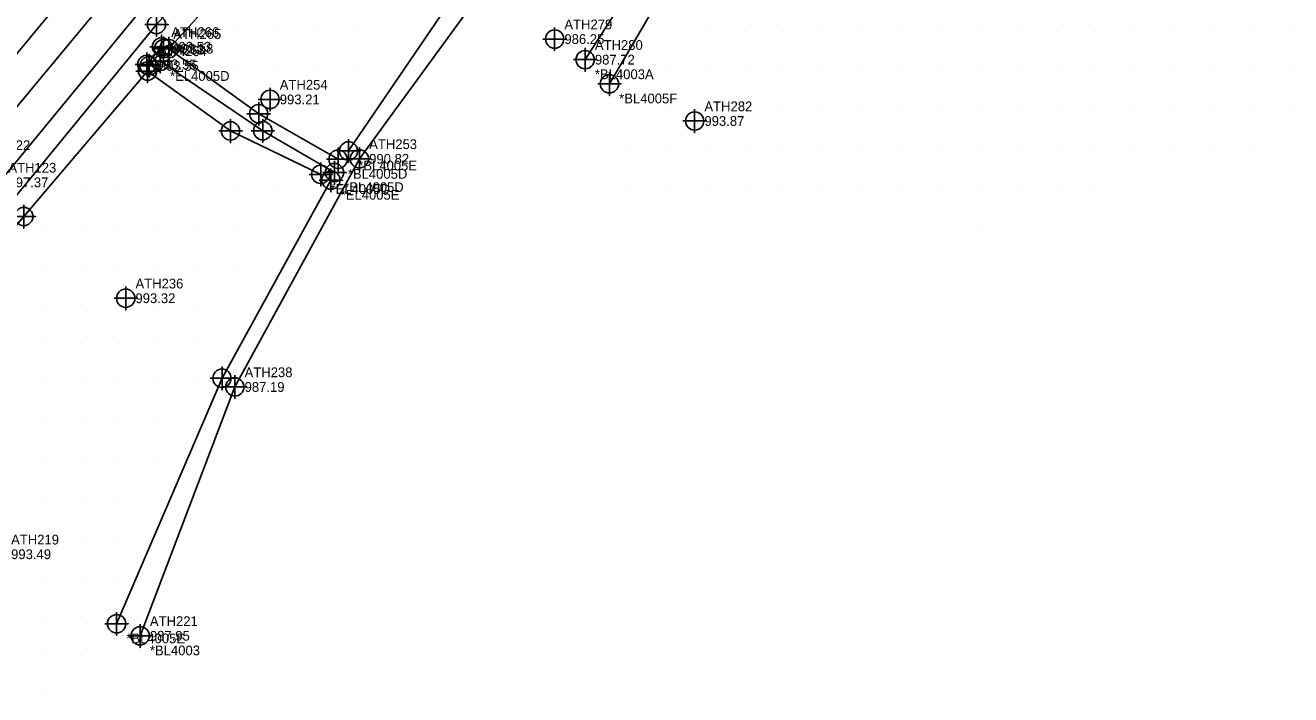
# Model space of a CAD drawing. Extents: x 1116680 to 1117499, y 661040 to 661703.
# Drawn here: x 1116855.8 to 1117180, y 661050 to 661221.5 of the extents above; entities that cross this region are included whole.
import ezdxf

# ---------------------------------------------------------------- set-up
doc = ezdxf.new("R2010")
doc.units = 0
for name, color, linetype in [('Exist DTM Breakline', 7, 'Continuous'), ('Exist DTM Breakline Cogo Comment', 7, 'Continuous'), ('Exist DTM Breakline Cogo Point CELL', 7, 'Continuous'), ('Exist DTM Crownline', 7, 'Continuous'), ('Exist DTM Crownline Cogo Number', 7, 'Continuous'), ('Exist DTM Drainline Cogo Comment', 7, 'Continuous'), ('Exist DTM Drainline Cogo Elevation', 7, 'Continuous'), ('Exist DTM Drainline Cogo Number', 7, 'Continuous'), ('Exist DTM Drainline Cogo Point CELL', 7, 'Continuous'), ('Exist DTM QL2 LIDAR Elevation Point', 7, 'Continuous'), ('Exist DTM Regular Point CELL', 7, 'Continuous'), ('Exist DTM Regular Point Cogo Elevation', 7, 'Continuous'), ('Exist DTM Regular Point Cogo Number', 7, 'Continuous'), ('Exist DTM Regular Point Underwater CELL', 7, 'Continuous'), ('Exist DTM Regular Point Underwater Cogo Elevation', 7, 'Continuous'), ('Exist DTM Regular Point Underwater Cogo Number', 7, 'Continuous'), ('Exist Hydro Stream or Body of Water', 7, 'Continuous'), ('Exist Roads EOP', 7, 'Continuous'), ('Exist Roads EOP Cogo Elevation', 7, 'Continuous'), ('Exist Roads EOP Cogo Number', 7, 'Continuous'), ('Exist Structure Major Bridge WW Cogo Elevation', 7, 'Continuous'), ('Exist Structure Major Bridge WW Cogo Number', 7, 'Continuous'), ('Exist Structure Major Bridge WW Cogo Point CELL', 7, 'Continuous')]:
    doc.layers.add(name, color=color, linetype=linetype)

msp = doc.modelspace()

# ---------------------------------------------------------------- linework, layer by layer
at = {"layer": 'Exist DTM Breakline'}
msp.add_line((1117005.474, 661206.472), (1117040.467, 661266.201), dxfattribs=at)
for points in [[(1116938.631, 661189.278), (1116970.08, 661235.53), (1117004.586, 661292.975), (1117022.365, 661331.868), (1117020.311, 661340.79)], [(1116804.214, 661119.184), (1116852.32, 661176.293), (1116889.45, 661221.661), (1116930.482, 661266.919), (1116979.857, 661313.491), (1117005.659, 661333.608)], [(1116935.96, 661187.155), (1116915.624, 661198.811), (1116892.595, 661215.476), (1116935.176, 661262.478), (1116985.662, 661308.46), (1117011.556, 661329.863)], [(1116886.991, 661211.443), (1116887.554, 661211.066), (1116891.271, 661215.491), (1116890.731, 661215.958), (1116886.991, 661211.443)], [(1116807.384, 661116.479), (1116855.455, 661172.483), (1116887.171, 661209.743), (1116908.403, 661194.399), (1116931.527, 661183.283)], [(1116935.041, 661183.755), (1116916.666, 661194.461), (1116890.415, 661212.237)], [(1116879.222, 661068.166), (1116906.229, 661131.057), (1116934.132, 661181.793)]]:
    msp.add_lwpolyline(points, dxfattribs=at)
at = {"layer": 'Exist DTM Breakline Cogo Point CELL'}
for points in [[(1116889.45, 661224.661), (1116889.45, 661218.661), (1116889.45, 661221.661), (1116892.45, 661221.661), (1116886.45, 661221.661)], [(1116892.595, 661218.476), (1116892.595, 661212.476), (1116892.595, 661215.476), (1116895.595, 661215.476), (1116889.595, 661215.476)], [(1116890.415, 661215.237), (1116890.415, 661209.237), (1116890.415, 661212.237), (1116893.415, 661212.237), (1116887.415, 661212.237)], [(1116887.171, 661212.743), (1116887.171, 661206.743), (1116887.171, 661209.743), (1116890.171, 661209.743), (1116884.171, 661209.743)], [(1117005.474, 661209.472), (1117005.474, 661203.472), (1117005.474, 661206.472), (1117008.474, 661206.472), (1117002.474, 661206.472)], [(1116915.624, 661201.811), (1116915.624, 661195.811), (1116915.624, 661198.811), (1116918.624, 661198.811), (1116912.624, 661198.811)], [(1116908.403, 661197.399), (1116908.403, 661191.399), (1116908.403, 661194.399), (1116911.403, 661194.399), (1116905.403, 661194.399)], [(1116916.666, 661197.461), (1116916.666, 661191.461), (1116916.666, 661194.461), (1116919.666, 661194.461), (1116913.666, 661194.461)], [(1116938.631, 661192.278), (1116938.631, 661186.278), (1116938.631, 661189.278), (1116941.631, 661189.278), (1116935.631, 661189.278)], [(1116935.96, 661190.155), (1116935.96, 661184.155), (1116935.96, 661187.155), (1116938.96, 661187.155), (1116932.96, 661187.155)], [(1116931.527, 661186.283), (1116931.527, 661180.283), (1116931.527, 661183.283), (1116934.527, 661183.283), (1116928.527, 661183.283)], [(1116934.132, 661184.793), (1116934.132, 661178.793), (1116934.132, 661181.793), (1116937.132, 661181.793), (1116931.132, 661181.793)], [(1116935.041, 661186.755), (1116935.041, 661180.755), (1116935.041, 661183.755), (1116938.041, 661183.755), (1116932.041, 661183.755)], [(1116855.455, 661175.483), (1116855.455, 661169.483), (1116855.455, 661172.483), (1116858.455, 661172.483), (1116852.455, 661172.483)], [(1116906.229, 661134.057), (1116906.229, 661128.057), (1116906.229, 661131.057), (1116909.229, 661131.057), (1116903.229, 661131.057)], [(1116879.222, 661071.166), (1116879.222, 661065.166), (1116879.222, 661068.166), (1116882.222, 661068.166), (1116876.222, 661068.166)]]:
    msp.add_lwpolyline(points, dxfattribs=at)
for centre in [(1116889.45, 661221.661), (1116892.595, 661215.476), (1116890.415, 661212.237), (1116887.171, 661209.743), (1117005.474, 661206.472), (1116915.624, 661198.811), (1116908.403, 661194.399), (1116916.666, 661194.461), (1116938.631, 661189.278), (1116935.96, 661187.155), (1116931.527, 661183.283), (1116934.132, 661181.793), (1116935.041, 661183.755), (1116855.455, 661172.483), (1116906.229, 661131.057), (1116879.222, 661068.166)]:
    msp.add_circle(centre, 2.344, dxfattribs=at)
at = {"layer": 'Exist DTM Crownline'}
msp.add_lwpolyline([(1116917.938, 661277.457), (1116878.296, 661230.271), (1116842.354, 661187.006), (1116792.558, 661125.963), (1116776.188, 661106.218)], dxfattribs=at)
at = {"layer": 'Exist DTM Drainline Cogo Point CELL'}
for points in [[(1116999.252, 661215.663), (1116999.252, 661209.663), (1116999.252, 661212.663), (1117002.252, 661212.663), (1116996.252, 661212.663)], [(1116941.429, 661190.261), (1116941.429, 661184.261), (1116941.429, 661187.261), (1116944.429, 661187.261), (1116938.429, 661187.261)], [(1116909.522, 661131.826), (1116909.522, 661125.826), (1116909.522, 661128.826), (1116912.522, 661128.826), (1116906.522, 661128.826)], [(1116885.259, 661068.084), (1116885.259, 661062.084), (1116885.259, 661065.084), (1116888.259, 661065.084), (1116882.259, 661065.084)]]:
    msp.add_lwpolyline(points, dxfattribs=at)
for centre in [(1116999.252, 661212.663), (1116941.429, 661187.261), (1116909.522, 661128.826), (1116885.259, 661065.084)]:
    msp.add_circle(centre, 2.344, dxfattribs=at)
at = {"layer": 'Exist DTM QL2 LIDAR Elevation Point'}
for p, q in [((1116910, 661220), (1116910, 661220)), ((1116920, 661220), (1116920, 661220)), ((1116930, 661220), (1116930, 661220)), ((1116940, 661220), (1116940, 661220)), ((1117030, 661220), (1117030, 661220)), ((1117040, 661220), (1117040, 661220)), ((1117050, 661220), (1117050, 661220)), ((1117060, 661220), (1117060, 661220)), ((1117070, 661220), (1117070, 661220)), ((1117080, 661220), (1117080, 661220)), ((1117090, 661220), (1117090, 661220)), ((1117100, 661220), (1117100, 661220)), ((1117110, 661220), (1117110, 661220)), ((1117120, 661220), (1117120, 661220)), ((1117130, 661220), (1117130, 661220)), ((1117140, 661220), (1117140, 661220)), ((1117150, 661220), (1117150, 661220)), ((1117160, 661220), (1117160, 661220)), ((1117170, 661220), (1117170, 661220)), ((1117180, 661220), (1117180, 661220)), ((1116910, 661210), (1116910, 661210)), ((1116920, 661210), (1116920, 661210)), ((1116930, 661210), (1116930, 661210)), ((1116940, 661210), (1116940, 661210)), ((1117020, 661210), (1117020, 661210)), ((1117030, 661210), (1117030, 661210)), ((1117040, 661210), (1117040, 661210)), ((1117050, 661210), (1117050, 661210)), ((1117060, 661210), (1117060, 661210)), ((1117070, 661210), (1117070, 661210)), ((1117080, 661210), (1117080, 661210)), ((1117090, 661210), (1117090, 661210)), ((1117100, 661210), (1117100, 661210)), ((1117110, 661210), (1117110, 661210)), ((1117120, 661210), (1117120, 661210)), ((1117130, 661210), (1117130, 661210)), ((1117140, 661210), (1117140, 661210)), ((1117150, 661210), (1117150, 661210)), ((1117160, 661210), (1117160, 661210)), ((1117170, 661210), (1117170, 661210)), ((1117180, 661210), (1117180, 661210)), ((1116890, 661200), (1116890, 661200)), ((1116900, 661200), (1116900, 661200)), ((1116920, 661200), (1116920, 661200)), ((1116930, 661200), (1116930, 661200)), ((1117020, 661200), (1117020, 661200)), ((1117030, 661200), (1117030, 661200)), ((1117040, 661200), (1117040, 661200)), ((1117050, 661200), (1117050, 661200)), ((1117060, 661200), (1117060, 661200)), ((1117070, 661200), (1117070, 661200)), ((1117080, 661200), (1117080, 661200)), ((1117090, 661200), (1117090, 661200)), ((1117100, 661200), (1117100, 661200)), ((1117110, 661200), (1117110, 661200)), ((1117120, 661200), (1117120, 661200)), ((1117130, 661200), (1117130, 661200)), ((1117140, 661200), (1117140, 661200)), ((1117150, 661200), (1117150, 661200)), ((1117160, 661200), (1117160, 661200)), ((1117170, 661200), (1117170, 661200)), ((1117180, 661200), (1117180, 661200)), ((1116880, 661190), (1116880, 661190)), ((1116890, 661190), (1116890, 661190)), ((1116900, 661190), (1116900, 661190)), ((1116910, 661190), (1116910, 661190)), ((1117010, 661190), (1117010, 661190)), ((1117020, 661190), (1117020, 661190)), ((1117030, 661190), (1117030, 661190)), ((1117040, 661190), (1117040, 661190)), ((1117050, 661190), (1117050, 661190)), ((1117060, 661190), (1117060, 661190)), ((1117070, 661190), (1117070, 661190)), ((1117080, 661190), (1117080, 661190)), ((1117090, 661190), (1117090, 661190)), ((1117100, 661190), (1117100, 661190)), ((1117110, 661190), (1117110, 661190)), ((1117120, 661190), (1117120, 661190)), ((1117130, 661190), (1117130, 661190)), ((1117140, 661190), (1117140, 661190)), ((1117150, 661190), (1117150, 661190)), ((1117160, 661190), (1117160, 661190)), ((1117170, 661190), (1117170, 661190)), ((1116870, 661180), (1116870, 661180)), ((1116880, 661180), (1116880, 661180)), ((1116890, 661180), (1116890, 661180)), ((1116900, 661180), (1116900, 661180)), ((1116910, 661180), (1116910, 661180)), ((1116920, 661180), (1116920, 661180)), ((1117010, 661180), (1117010, 661180)), ((1117020, 661180), (1117020, 661180)), ((1117030, 661180), (1117030, 661180)), ((1117040, 661180), (1117040, 661180)), ((1117050, 661180), (1117050, 661180)), ((1117060, 661180), (1117060, 661180)), ((1117070, 661180), (1117070, 661180)), ((1117080, 661180), (1117080, 661180)), ((1117090, 661180), (1117090, 661180)), ((1117100, 661180), (1117100, 661180)), ((1117110, 661180), (1117110, 661180)), ((1117120, 661180), (1117120, 661180)), ((1117130, 661180), (1117130, 661180)), ((1116860, 661170), (1116860, 661170)), ((1116870, 661170), (1116870, 661170)), ((1116880, 661170), (1116880, 661170)), ((1116890, 661170), (1116890, 661170)), ((1116900, 661170), (1116900, 661170)), ((1116910, 661170), (1116910, 661170)), ((1117100, 661170), (1117100, 661170)), ((1116860, 661160), (1116860, 661160)), ((1116870, 661160), (1116870, 661160)), ((1116880, 661160), (1116880, 661160)), ((1116890, 661160), (1116890, 661160)), ((1116900, 661160), (1116900, 661160)), ((1116910, 661160), (1116910, 661160)), ((1116860, 661150), (1116860, 661150)), ((1116870, 661150), (1116870, 661150)), ((1116880, 661150), (1116880, 661150)), ((1116890, 661150), (1116890, 661150)), ((1116900, 661150), (1116900, 661150)), ((1116860, 661140), (1116860, 661140)), ((1116870, 661140), (1116870, 661140)), ((1116880, 661140), (1116880, 661140)), ((1116890, 661140), (1116890, 661140)), ((1116900, 661140), (1116900, 661140)), ((1116860, 661130), (1116860, 661130)), ((1116870, 661130), (1116870, 661130)), ((1116880, 661130), (1116880, 661130)), ((1116890, 661130), (1116890, 661130)), ((1116900, 661130), (1116900, 661130)), ((1116860, 661120), (1116860, 661120)), ((1116870, 661120), (1116870, 661120)), ((1116880, 661120), (1116880, 661120)), ((1116890, 661120), (1116890, 661120)), ((1116860, 661110), (1116860, 661110)), ((1116870, 661110), (1116870, 661110)), ((1116880, 661110), (1116880, 661110)), ((1116890, 661110), (1116890, 661110)), ((1116860, 661100), (1116860, 661100)), ((1116870, 661100), (1116870, 661100)), ((1116880, 661100), (1116880, 661100)), ((1116860, 661090), (1116860, 661090)), ((1116870, 661090), (1116870, 661090)), ((1116880, 661090), (1116880, 661090)), ((1116860, 661080), (1116860, 661080)), ((1116870, 661080), (1116870, 661080)), ((1116880, 661080), (1116880, 661080)), ((1116860, 661070), (1116860, 661070)), ((1116870, 661070), (1116870, 661070)), ((1116860, 661060), (1116860, 661060)), ((1116870, 661060), (1116870, 661060)), ((1116860, 661050), (1116860, 661050))]:
    msp.add_line(p, q, dxfattribs=at)
at = {"layer": 'Exist DTM Regular Point CELL'}
for points in [[(1116918.53, 661205.476), (1116918.53, 661199.476), (1116918.53, 661202.476), (1116921.53, 661202.476), (1116915.53, 661202.476)], [(1117027.311, 661199.953), (1117027.311, 661193.953), (1117027.311, 661196.953), (1117030.311, 661196.953), (1117024.311, 661196.953)], [(1116881.562, 661154.554), (1116881.562, 661148.554), (1116881.562, 661151.554), (1116884.562, 661151.554), (1116878.562, 661151.554)]]:
    msp.add_lwpolyline(points, dxfattribs=at)
for centre in [(1116918.53, 661202.476), (1117027.311, 661196.953), (1116881.562, 661151.554)]:
    msp.add_circle(centre, 2.344, dxfattribs=at)
at = {"layer": 'Exist DTM Regular Point Underwater CELL'}
msp.add_lwpolyline([(1116991.441, 661220.931), (1116991.441, 661214.931), (1116991.441, 661217.931), (1116994.441, 661217.931), (1116988.441, 661217.931)], dxfattribs=at)
msp.add_circle((1116991.441, 661217.931), 2.344, dxfattribs=at)
at = {"layer": 'Exist Hydro Stream or Body of Water'}
for points in [[(1116885.259, 661065.084), (1116909.522, 661128.826), (1116941.429, 661187.261), (1116973.299, 661231.015), (1117008.806, 661288.675), (1117028.625, 661329.39), (1117037.259, 661346.044), (1117054.084, 661350.959), (1117065.864, 661380.085), (1117058.435, 661381.413), (1117066.561, 661417.266), (1117077.352, 661449.252), (1117098.924, 661488.98)], [(1116999.252, 661212.663), (1117035.553, 661269.03), (1117067.842, 661309.057), (1117080.473, 661351.773), (1117079.751, 661359.687), (1117095.986, 661391.983), (1117110.725, 661432.453), (1117125.362, 661468.034)]]:
    msp.add_lwpolyline(points, dxfattribs=at)
at = {"layer": 'Exist Roads EOP'}
for points in [[(1116925.984, 661301.817), (1116910.969, 661283.553), (1116871.822, 661236.252), (1116835.673, 661192.44), (1116785.819, 661131.962), (1116768.893, 661111.563)], [(1116924.898, 661271.684), (1116885.096, 661224.926), (1116849.016, 661181.231), (1116799.444, 661121.119), (1116782.519, 661100.642)]]:
    msp.add_lwpolyline(points, dxfattribs=at)
at = {"layer": 'Exist Structure Major Bridge WW Cogo Point CELL'}
for points in [[(1116887.731, 661215.958), (1116893.731, 661215.958), (1116890.731, 661215.958), (1116890.731, 661218.958), (1116890.731, 661212.958)], [(1116888.271, 661215.491), (1116894.271, 661215.491), (1116891.271, 661215.491), (1116891.271, 661218.491), (1116891.271, 661212.491)], [(1116883.991, 661211.443), (1116889.991, 661211.443), (1116886.991, 661211.443), (1116886.991, 661214.443), (1116886.991, 661208.443)], [(1116884.554, 661211.066), (1116890.554, 661211.066), (1116887.554, 661211.066), (1116887.554, 661214.066), (1116887.554, 661208.066)]]:
    msp.add_lwpolyline(points, dxfattribs=at)
for centre in [(1116890.731, 661215.958), (1116891.271, 661215.491), (1116886.991, 661211.443), (1116887.554, 661211.066)]:
    msp.add_circle(centre, 2.344, dxfattribs=at)

# ---------------------------------------------------------------- texts
at = {"layer": 'Exist DTM Breakline Cogo Comment'}
for s, p in [('*EL4005D', (1116892.915, 661207.237)), ('*BL4005F', (1117007.974, 661201.472)), ('*BL4005D', (1116938.46, 661182.155)), ('*BL4005E', (1116941.131, 661184.278)), ('*EL4005D', (1116934.027, 661178.283)), ('*BL4005D', (1116937.541, 661178.755)), ('*EL4005E', (1116936.632, 661176.793)), ('*BL4005E', (1116881.722, 661063.166))]:
    msp.add_text(s, height=2.5, dxfattribs=at).set_placement(p)
at = {"layer": 'Exist DTM Crownline Cogo Number'}
msp.add_text('ATH122', height=2.5, dxfattribs=at).set_placement((1116844.854, 661189.506))
at = {"layer": 'Exist DTM Drainline Cogo Comment'}
for s, p in [('*BL4003A', (1117001.752, 661207.663)), ('*BL4003', (1116887.759, 661060.084))]:
    msp.add_text(s, height=2.5, dxfattribs=at).set_placement(p)
at = {"layer": 'Exist DTM Drainline Cogo Elevation'}
for s, p in [('987.72', (1117001.752, 661211.413)), ('990.82', (1116943.929, 661186.011)), ('987.19', (1116912.022, 661127.576)), ('987.95', (1116887.759, 661063.834))]:
    msp.add_text(s, height=2.5, dxfattribs=at).set_placement(p)
at = {"layer": 'Exist DTM Drainline Cogo Number'}
for s, p in [('ATH280', (1117001.752, 661215.163)), ('ATH253', (1116943.929, 661189.761)), ('ATH238', (1116912.022, 661131.326)), ('ATH221', (1116887.759, 661067.584))]:
    msp.add_text(s, height=2.5, dxfattribs=at).set_placement(p)
at = {"layer": 'Exist DTM Regular Point Cogo Elevation'}
for s, p in [('993.21', (1116921.03, 661201.226)), ('993.87', (1117029.811, 661195.703)), ('993.32', (1116884.062, 661150.304)), ('993.49', (1116852.202, 661084.728))]:
    msp.add_text(s, height=2.5, dxfattribs=at).set_placement(p)
at = {"layer": 'Exist DTM Regular Point Cogo Number'}
for s, p in [('ATH254', (1116921.03, 661204.976)), ('ATH282', (1117029.811, 661199.453)), ('ATH236', (1116884.062, 661154.054)), ('ATH219', (1116852.202, 661088.478))]:
    msp.add_text(s, height=2.5, dxfattribs=at).set_placement(p)
at = {"layer": 'Exist DTM Regular Point Underwater Cogo Elevation'}
msp.add_text('986.25', height=2.5, dxfattribs=at).set_placement((1116993.941, 661216.681))
at = {"layer": 'Exist DTM Regular Point Underwater Cogo Number'}
msp.add_text('ATH279', height=2.5, dxfattribs=at).set_placement((1116993.941, 661220.431))
at = {"layer": 'Exist Roads EOP Cogo Elevation'}
msp.add_text('997.37', height=2.5, dxfattribs=at).set_placement((1116851.516, 661179.981))
at = {"layer": 'Exist Roads EOP Cogo Number'}
msp.add_text('ATH123', height=2.5, dxfattribs=at).set_placement((1116851.516, 661183.731))
at = {"layer": 'Exist Structure Major Bridge WW Cogo Elevation'}
for s, p in [('993.53', (1116893.231, 661214.708)), ('993.58', (1116893.771, 661214.241)), ('993.55', (1116889.491, 661210.193)), ('993.55', (1116890.054, 661209.816))]:
    msp.add_text(s, height=2.5, dxfattribs=at).set_placement(p)
at = {"layer": 'Exist Structure Major Bridge WW Cogo Number'}
for s, p in [('ATH266', (1116893.231, 661218.458)), ('ATH265', (1116893.771, 661217.991)), ('ATH263', (1116889.491, 661213.943)), ('ATH264', (1116890.054, 661213.566))]:
    msp.add_text(s, height=2.5, dxfattribs=at).set_placement(p)

doc.saveas('drawing.dxf')
